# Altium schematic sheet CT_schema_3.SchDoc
size 276 x 169 mm
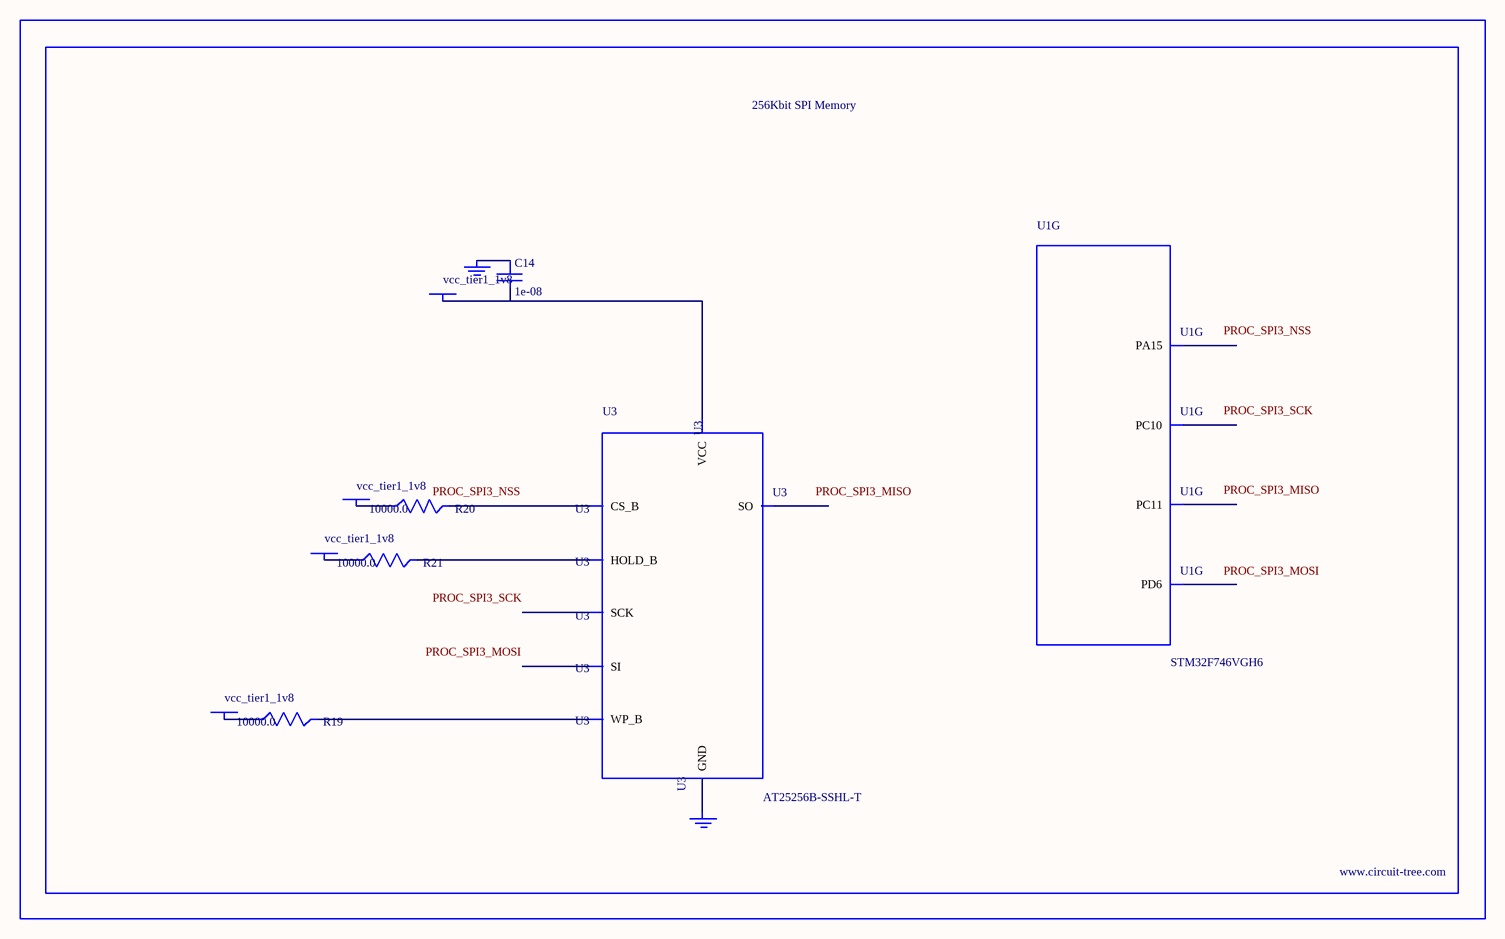
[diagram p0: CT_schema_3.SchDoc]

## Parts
BORDER2  (no value)
C14  1e-08  [C0402]
GND_INSTANCE_2_0  (no value)
GND_INSTANCE_2_1  (no value)
POWER_INSTANCE_2_0  vcc_tier1_1v8
POWER_INSTANCE_2_1  vcc_tier1_1v8
POWER_INSTANCE_2_2  vcc_tier1_1v8
POWER_INSTANCE_2_3  vcc_tier1_1v8
R19  10000.0  [R0603]
R20  10000.0  [R0603]
R21  10000.0  [R0603]
U1  STM32F746VGH6  [TFBGA100]  (part G of 10)
U3  AT25256B-SSHL-T  [SOIC-8]

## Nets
NetC14_1: C14.1 GND_INSTANCE_2_0.0(GND)
NetC14_2: C14.2 POWER_INSTANCE_2_3.0(PWR) U3.8(VCC)
NetGND_INSTANCE_2_1_0: GND_INSTANCE_2_1.0(GND) U3.4(GND)
NetPOWER_INSTANCE_2_0_0: POWER_INSTANCE_2_0.0(PWR) R20.1
NetPOWER_INSTANCE_2_1_0: POWER_INSTANCE_2_1.0(PWR) R19.1
NetPOWER_INSTANCE_2_2_0: POWER_INSTANCE_2_2.0(PWR) R21.1
NetR19_2: R19.2 U3.3(WP_B)
NetR20_2: R20.2 U3.1(CS_B)
NetR21_2: R21.2 U3.7(HOLD_B)

Not connected (* = marked no-connect by the designer): U1 A8(PA15) B8(PC11) B9(PC10) C6(PD6); U3 2(SO) 5(SI) 6(SCK)

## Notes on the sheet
- Labels drawn without touching a wire or pin: PROC_SPI3_MISO, PROC_SPI3_MOSI, PROC_SPI3_NSS, PROC_SPI3_SCK

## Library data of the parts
BORDER2 = BORDER_PAGE2
C14 = C0402C103K3RAC
GND_INSTANCE_2_0 GND_INSTANCE_2_1 = GND
POWER_INSTANCE_2_0-POWER_INSTANCE_2_3 = PWR
R19-R21 = RC0603JR-0710KL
